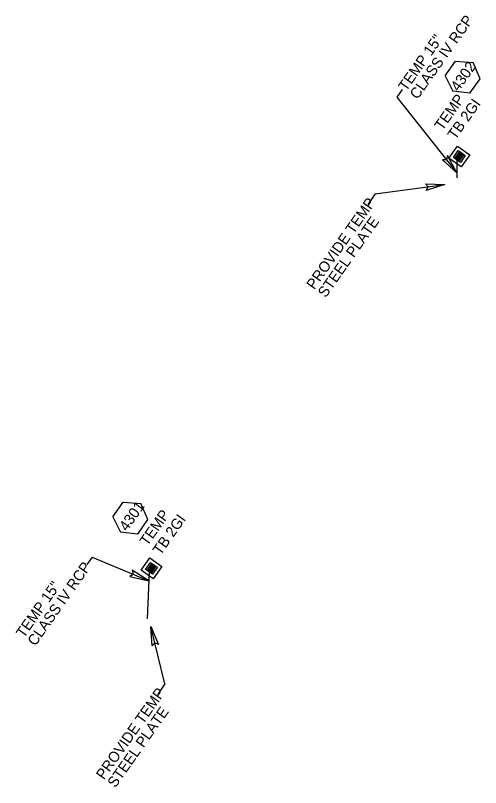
# Model space of a CAD drawing. Extents: x 2214419 to 2238519, y 983271 to 1015868.
# Drawn here: x 2216735.8 to 2216954.8, y 986575.7 to 986939.2 of the extents above; entities that cross this region are included whole.
import ezdxf

# ---------------------------------------------------------------- set-up
doc = ezdxf.new("R2010")
doc.units = 0
for name, color, linetype in [('Prop Drainage Structure Box Number Symbol CELL', 7, 'Continuous'), ('Prop Drainage Structure Drop Inlet Grate 2 Wide Slots and Sag Grates 840 22 TB CELL', 7, 'Continuous'), ('Prop Drainage Structure Drop Inlet Grate 2 Wide Slots and Sag Grates 840 22 TB Label', 7, 'Continuous'), ('Prop Drainage Structure Pipe Alternate 15in', 7, 'Continuous'), ('Prop Drainage Structure Pipe RCP 15in Class IV', 7, 'Continuous'), ('Prop Drainage Structure Plot Symbol 20 Scale', 7, 'Continuous'), ('Prop Drainage Structure Plot Symbol 50 Scale', 7, 'Continuous'), ('Prop Plan Preparation Drainage Notes Label', 7, 'Continuous')]:
    doc.layers.add(name, color=color, linetype=linetype)

msp = doc.modelspace()

# ---------------------------------------------------------------- linework, layer by layer
at = {"layer": 'Prop Drainage Structure Box Number Symbol CELL'}
for p, q in [((2216938.16, 986910.8), (2216942.99, 986917.67)), ((2216942.99, 986917.67), (2216951.29, 986917.04)), ((2216954.66, 986909.44), (2216951.29, 986917.04)), ((2216938.16, 986910.8), (2216941.67, 986903.53)), ((2216949.82, 986902.58), (2216954.66, 986909.44)), ((2216949.82, 986902.58), (2216941.67, 986903.53)), ((2216781.69, 986703.24), (2216786.53, 986710.1)), ((2216786.53, 986710.1), (2216794.82, 986709.48)), ((2216798.2, 986701.88), (2216794.82, 986709.48)), ((2216781.69, 986703.24), (2216785.21, 986695.96)), ((2216793.36, 986695.01), (2216798.2, 986701.88)), ((2216793.36, 986695.01), (2216785.21, 986695.96))]:
    msp.add_line(p, q, dxfattribs=at)
at = {"layer": 'Prop Drainage Structure Drop Inlet Grate 2 Wide Slots and Sag Grates 840 22 TB CELL'}
for p, q in [((2216945.96, 986874.46), (2216945.96, 986874.46)), ((2216943.65, 986871.19), (2216943.65, 986871.19)), ((2216943.85, 986873.5), (2216943.85, 986873.5)), ((2216944.81, 986872.82), (2216944.81, 986872.82)), ((2216945.76, 986872.15), (2216945.76, 986872.15)), ((2216798.91, 986679.62), (2216798.91, 986679.62)), ((2216799.86, 986678.95), (2216799.86, 986678.95)), ((2216800.82, 986678.27), (2216800.82, 986678.27)), ((2216801.01, 986680.58), (2216801.01, 986680.58)), ((2216798.71, 986677.31), (2216798.71, 986677.31))]:
    msp.add_line(p, q, dxfattribs=at)
for points in [[(2216946.91, 986873.79), (2216944.61, 986870.52), (2216942.7, 986871.86), (2216945, 986875.13), (2216946.91, 986873.79)], [(2216946.82, 986873.77), (2216944.59, 986870.6), (2216942.79, 986871.88), (2216945.02, 986875.04), (2216946.82, 986873.77), (2216946.82, 986873.77)], [(2216946.81, 986873.77), (2216945.71, 986872.2), (2216943.92, 986873.46), (2216945.02, 986875.03), (2216946.81, 986873.77)], [(2216944.82, 986873.95), (2216944.34, 986873.27), (2216944.12, 986873.42), (2216944.6, 986874.1), (2216944.82, 986873.95)], [(2216945.35, 986874.7), (2216944.87, 986874.01), (2216944.65, 986874.17), (2216945.13, 986874.85), (2216945.35, 986874.7)], [(2216945.66, 986874.47), (2216945.18, 986873.79), (2216944.96, 986873.95), (2216945.44, 986874.63), (2216945.66, 986874.47)], [(2216945.98, 986874.25), (2216945.5, 986873.57), (2216945.28, 986873.73), (2216945.76, 986874.41), (2216945.98, 986874.25)], [(2216946.29, 986874.03), (2216945.81, 986873.35), (2216945.59, 986873.5), (2216946.07, 986874.19), (2216946.29, 986874.03)], [(2216945.69, 986872.18), (2216944.59, 986870.62), (2216942.8, 986871.88), (2216943.91, 986873.44), (2216945.69, 986872.18)], [(2216943.7, 986872.36), (2216943.22, 986871.68), (2216943, 986871.84), (2216943.48, 986872.52), (2216943.7, 986872.36)], [(2216944.02, 986872.14), (2216943.54, 986871.46), (2216943.32, 986871.62), (2216943.8, 986872.3), (2216944.02, 986872.14)], [(2216944.23, 986873.11), (2216943.75, 986872.43), (2216943.53, 986872.59), (2216944.01, 986873.27), (2216944.23, 986873.11)], [(2216944.33, 986871.92), (2216943.85, 986871.24), (2216943.63, 986871.39), (2216944.11, 986872.08), (2216944.33, 986871.92)], [(2216944.55, 986872.89), (2216944.07, 986872.21), (2216943.85, 986872.37), (2216944.33, 986873.05), (2216944.55, 986872.89)], [(2216944.65, 986871.7), (2216944.17, 986871.02), (2216943.95, 986871.17), (2216944.43, 986871.85), (2216944.65, 986871.7)], [(2216944.86, 986872.67), (2216944.38, 986871.99), (2216944.16, 986872.14), (2216944.64, 986872.82), (2216944.86, 986872.67)], [(2216944.96, 986871.48), (2216944.48, 986870.79), (2216944.26, 986870.95), (2216944.74, 986871.63), (2216944.96, 986871.48)], [(2216945.14, 986873.72), (2216944.66, 986873.04), (2216944.43, 986873.2), (2216944.91, 986873.88), (2216945.14, 986873.72)], [(2216945.18, 986872.45), (2216944.7, 986871.77), (2216944.48, 986871.92), (2216944.96, 986872.6), (2216945.18, 986872.45)], [(2216945.45, 986873.5), (2216944.97, 986872.82), (2216944.75, 986872.98), (2216945.23, 986873.66), (2216945.45, 986873.5)], [(2216945.49, 986872.22), (2216945.01, 986871.54), (2216944.79, 986871.7), (2216945.27, 986872.38), (2216945.49, 986872.22)], [(2216945.77, 986873.28), (2216945.29, 986872.6), (2216945.06, 986872.76), (2216945.54, 986873.44), (2216945.77, 986873.28)], [(2216946.08, 986873.06), (2216945.6, 986872.38), (2216945.38, 986872.53), (2216945.86, 986873.21), (2216946.08, 986873.06)], [(2216946.61, 986873.81), (2216946.13, 986873.13), (2216945.91, 986873.28), (2216946.39, 986873.96), (2216946.61, 986873.81)], [(2216801.97, 986679.91), (2216799.66, 986676.64), (2216797.76, 986677.98), (2216800.06, 986681.25), (2216801.97, 986679.91)], [(2216801.88, 986679.89), (2216799.65, 986676.73), (2216797.84, 986678), (2216800.08, 986681.17), (2216801.88, 986679.89), (2216801.88, 986679.89)], [(2216800.75, 986678.31), (2216799.65, 986676.74), (2216797.86, 986678), (2216798.96, 986679.57), (2216800.75, 986678.31)], [(2216798.76, 986678.49), (2216798.28, 986677.81), (2216798.06, 986677.96), (2216798.54, 986678.64), (2216798.76, 986678.49)], [(2216799.08, 986678.26), (2216798.6, 986677.58), (2216798.37, 986677.74), (2216798.85, 986678.42), (2216799.08, 986678.26)], [(2216799.29, 986679.24), (2216798.81, 986678.55), (2216798.59, 986678.71), (2216799.07, 986679.39), (2216799.29, 986679.24)], [(2216799.39, 986678.04), (2216798.91, 986677.36), (2216798.69, 986677.52), (2216799.17, 986678.2), (2216799.39, 986678.04)], [(2216799.6, 986679.01), (2216799.12, 986678.33), (2216798.9, 986678.49), (2216799.38, 986679.17), (2216799.6, 986679.01)], [(2216801.87, 986679.89), (2216800.76, 986678.32), (2216798.97, 986679.59), (2216800.08, 986681.15), (2216801.87, 986679.89)], [(2216799.71, 986677.82), (2216799.23, 986677.14), (2216799, 986677.3), (2216799.48, 986677.98), (2216799.71, 986677.82)], [(2216799.88, 986680.07), (2216799.4, 986679.39), (2216799.18, 986679.55), (2216799.66, 986680.23), (2216799.88, 986680.07)], [(2216799.92, 986678.79), (2216799.44, 986678.11), (2216799.22, 986678.27), (2216799.7, 986678.95), (2216799.92, 986678.79)], [(2216800.19, 986679.85), (2216799.71, 986679.17), (2216799.49, 986679.32), (2216799.97, 986680), (2216800.19, 986679.85)], [(2216800.23, 986678.57), (2216799.75, 986677.89), (2216799.53, 986678.04), (2216800.01, 986678.73), (2216800.23, 986678.57)], [(2216800.4, 986680.82), (2216799.92, 986680.14), (2216799.7, 986680.29), (2216800.18, 986680.98), (2216800.4, 986680.82)], [(2216800.51, 986679.63), (2216800.03, 986678.95), (2216799.81, 986679.1), (2216800.29, 986679.78), (2216800.51, 986679.63)], [(2216800.55, 986678.35), (2216800.07, 986677.67), (2216799.85, 986677.82), (2216800.33, 986678.5), (2216800.55, 986678.35)], [(2216800.72, 986680.6), (2216800.24, 986679.92), (2216800.02, 986680.07), (2216800.5, 986680.75), (2216800.72, 986680.6)], [(2216800.82, 986679.4), (2216800.34, 986678.72), (2216800.12, 986678.88), (2216800.6, 986679.56), (2216800.82, 986679.4)], [(2216801.03, 986680.38), (2216800.55, 986679.69), (2216800.33, 986679.85), (2216800.81, 986680.53), (2216801.03, 986680.38)], [(2216801.14, 986679.18), (2216800.66, 986678.5), (2216800.44, 986678.66), (2216800.92, 986679.34), (2216801.14, 986679.18)], [(2216801.35, 986680.15), (2216800.87, 986679.47), (2216800.65, 986679.63), (2216801.13, 986680.31), (2216801.35, 986680.15)], [(2216801.66, 986679.93), (2216801.18, 986679.25), (2216800.96, 986679.41), (2216801.44, 986680.09), (2216801.66, 986679.93)], [(2216800.02, 986677.6), (2216799.54, 986676.92), (2216799.32, 986677.07), (2216799.8, 986677.75), (2216800.02, 986677.6)]]:
    msp.add_lwpolyline(points, dxfattribs=at)
at = {"layer": 'Prop Drainage Structure Pipe Alternate 15in'}
msp.add_line((2216943.65, 986871.19), (2216943.68, 986862.8), dxfattribs=at)
at = {"layer": 'Prop Drainage Structure Pipe RCP 15in Class IV'}
msp.add_line((2216798.71, 986677.31), (2216797.79, 986655.14), dxfattribs=at)
at = {"layer": 'Prop Drainage Structure Plot Symbol 20 Scale'}
for points in [[(2216947.59, 986873.31), (2216945.29, 986870.04), (2216942.02, 986872.34), (2216944.32, 986875.61)], [(2216802.65, 986679.43), (2216800.34, 986676.16), (2216797.07, 986678.46), (2216799.38, 986681.73)]]:
    msp.add_lwpolyline(points, close=True, dxfattribs=at)
at = {"layer": 'Prop Drainage Structure Plot Symbol 50 Scale'}
for points in [[(2216949.68, 986873.67), (2216945.65, 986867.95), (2216939.93, 986871.98), (2216943.96, 986877.7)], [(2216804.74, 986679.79), (2216800.71, 986674.07), (2216794.98, 986678.1), (2216799.02, 986683.82)]]:
    msp.add_lwpolyline(points, close=True, dxfattribs=at)
at = {"layer": 'Prop Plan Preparation Drainage Notes Label'}
for p, q in [((2216917.84, 986904.3), (2216915.37, 986900.79)), ((2216915.37, 986900.79), (2216943.68, 986865.14)), ((2216905.25, 986855.25), (2216938.02, 986859.63)), ((2216905.25, 986855.25), (2216901.69, 986850.2)), ((2216771.95, 986684.21), (2216769.48, 986680.7)), ((2216771.95, 986684.21), (2216798.53, 986673.05)), ((2216806.19, 986624.51), (2216799.5, 986651.49)), ((2216806.19, 986624.51), (2216802.63, 986619.46))]:
    msp.add_line(p, q, dxfattribs=at)
for points in [[(2216936.87, 986871.23), (2216943.68, 986865.14), (2216939.3, 986873.22), (2216938.76, 986871.33)], [(2216928.89, 986859.98), (2216938.02, 986859.63), (2216929.26, 986856.85), (2216930.19, 986858.59)], [(2216789.64, 986675.1), (2216798.53, 986673.05), (2216790.81, 986678.03), (2216791.25, 986676.11)], [(2216800.16, 986642.38), (2216799.5, 986651.49), (2216803.23, 986643.09), (2216801.4, 986643.82)]]:
    msp.add_lwpolyline(points, close=True, dxfattribs=at)

# ---------------------------------------------------------------- texts
at = {"layer": 'Prop Drainage Structure Box Number Symbol CELL'}
for s, p in [('4302', (2216944.4, 986903.09)), ('4301', (2216788.31, 986696.05))]:
    msp.add_text(s, height=5, rotation=54.8168, dxfattribs=at).set_placement(p)
at = {"layer": 'Prop Drainage Structure Drop Inlet Grate 2 Wide Slots and Sag Grates 840 22 TB Label'}
for s, p in [('TEMP', (2216936.82, 986884.72)), ('TB 2GI', (2216942.95, 986880.4)), ('TEMP', (2216797.98, 986689.1)), ('TB 2GI', (2216804.11, 986684.78))]:
    msp.add_text(s, height=5, rotation=54.8168, dxfattribs=at).set_placement(p)
at = {"layer": 'Prop Plan Preparation Drainage Notes Label'}
for s, rotation, p in [('CLASS IV RCP', 54.8732, (2216925.15, 986899.42)), ('TEMP 15"', 54.8732, (2216919.79, 986903.19)), ('PROVIDE TEMP', 54.8307, (2216876.51, 986809.83)), ('STEEL PLATE', 54.8307, (2216881.87, 986806.05)), ('CLASS IV RCP', 54.8732, (2216745.16, 986642.03)), ('TEMP 15"', 54.8732, (2216739.8, 986645.8)), ('PROVIDE TEMP', 54.8307, (2216777.45, 986579.09)), ('STEEL PLATE', 54.8307, (2216782.81, 986575.31))]:
    msp.add_text(s, height=5, rotation=rotation, dxfattribs=at).set_placement(p)

doc.saveas('drawing.dxf')
